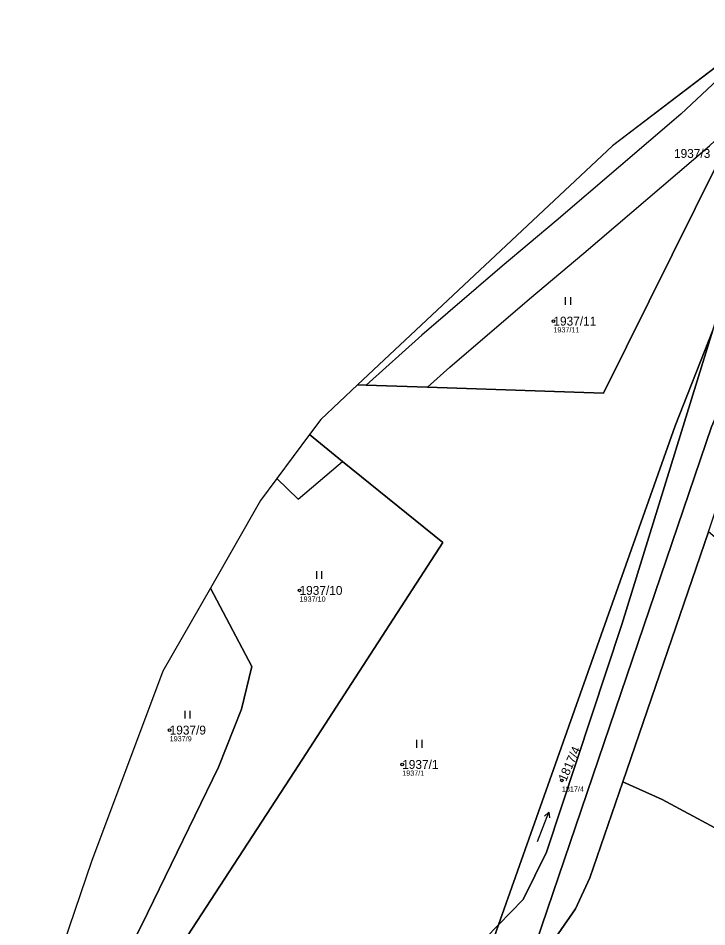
# Model space of a CAD drawing. Extents: x -762274 to -759271, y -1061928 to -1059060.
# Drawn here: x -761676.8 to -761545, y -1061110.9 to -1060936.9 of the extents above; entities that cross this region are included whole.
import ezdxf

# ---------------------------------------------------------------- set-up
doc = ezdxf.new("R2010")
doc.units = 0
for name, color, linetype in [('Definiční body', 7, 'Continuous'), ('Hranice parcel', 7, 'Continuous'), ('Parcelní čísla', 7, 'Continuous'), ('Polygon ku', 7, 'Continuous'), ('Polygon parcely', 7, 'Continuous'), ('Věcná břemena k části', 7, 'Continuous'), ('Značky kultur', 7, 'Continuous')]:
    doc.layers.add(name, color=color, linetype=linetype)

msp = doc.modelspace()

# ---------------------------------------------------------------- linework, layer by layer
at = {"layer": 'Definiční body'}
for centre in [(-761574.37, -1060994.9), (-761622.98, -1061046.45), (-761647.85, -1061073.19), (-761603.32, -1061079.77), (-761572.74, -1061082.82)]:
    msp.add_circle(centre, 0.25, dxfattribs=at)
at = {"layer": 'Hranice parcel'}
for p, q in [((-761530.99, -1060936.9), (-761563.04, -1060961.34)), ((-761563.04, -1060961.34), (-761611.9, -1061007.12)), ((-761611.9, -1061007.12), (-761618.93, -1061013.71)), ((-761618.93, -1061013.71), (-761621.08, -1061016.62)), ((-761561.09, -1061083.11), (-761544.65, -1061035.26)), ((-761640.03, -1061045.99), (-761649.18, -1061061.93))]:
    msp.add_line(p, q, dxfattribs=at)
for points in [[(-761529.96, -1060939.02), (-761538.5, -1060955.71), (-761564.75, -1061008.67), (-761598.46, -1061007.56), (-761610.24, -1061007.17), (-761611.9, -1061007.12)], [(-761580.84, -1061120.41), (-761578.73, -1061117.07), (-761544.07, -1061015.12), (-761528.37, -1060979.24)], [(-761584.85, -1061110.5), (-761551.04, -1061014.93), (-761543.87, -1060996.64)], [(-761543.87, -1060996.64), (-761561.28, -1061052.99), (-761575.72, -1061096.53), (-761580.18, -1061105.64), (-761584.85, -1061110.5)], [(-761621.08, -1061016.62), (-761614.73, -1061021.75), (-761595.52, -1061037.25), (-761623.93, -1061081.12), (-761655.13, -1061129.07)], [(-761621.08, -1061016.62), (-761627.31, -1061025.05), (-761630.42, -1061029.26), (-761640.03, -1061045.99)], [(-761665.3, -1061133.96), (-761663.29, -1061130.97), (-761652.11, -1061108.27), (-761638.48, -1061080.32), (-761634.06, -1061069.21), (-761632.14, -1061061.04), (-761640.03, -1061045.99)], [(-761649.18, -1061061.93), (-761662.78, -1061098.32), (-761676.85, -1061139.64)], [(-761561.09, -1061083.11), (-761567.39, -1061101.46), (-761570.16, -1061107.4), (-761576.79, -1061117.01), (-761580.84, -1061120.41)], [(-761522.28, -1061104.91), (-761543.48, -1061091.91), (-761553.56, -1061086.48), (-761561.09, -1061083.11)], [(-761652.06, -1061133.33), (-761641.24, -1061127.91), (-761631.73, -1061125.43), (-761598.48, -1061119.29), (-761592.46, -1061117.03), (-761587.41, -1061113.06), (-761584.85, -1061110.5)], [(-761584.85, -1061110.5), (-761586.2, -1061114.32), (-761599.26, -1061132.85)]]:
    msp.add_lwpolyline(points, dxfattribs=at)
at = {"layer": 'Polygon ku'}
msp.add_lwpolyline([(-761530.99, -1060936.9), (-761563.04, -1060961.34), (-761611.9, -1061007.12), (-761618.93, -1061013.71), (-761621.08, -1061016.62), (-761627.31, -1061025.05), (-761630.42, -1061029.26), (-761640.03, -1061045.99), (-761649.18, -1061061.93), (-761662.78, -1061098.32), (-761676.85, -1061139.64)], dxfattribs=at)
at = {"layer": 'Polygon parcely'}
for points in [[(-761529.96, -1060939.02), (-761530.99, -1060936.9), (-761563.04, -1060961.34), (-761611.9, -1061007.12), (-761610.24, -1061007.17), (-761598.46, -1061007.56), (-761564.75, -1061008.67), (-761538.5, -1060955.71)], [(-761614.73, -1061021.75), (-761595.52, -1061037.25), (-761623.93, -1061081.12), (-761655.13, -1061129.07), (-761652.06, -1061133.33), (-761641.24, -1061127.91), (-761631.73, -1061125.43), (-761598.48, -1061119.29), (-761592.46, -1061117.03), (-761587.41, -1061113.06), (-761584.85, -1061110.5), (-761551.04, -1061014.93), (-761543.87, -1060996.64), (-761528.96, -1060950.6), (-761526.37, -1060946.41), (-761526.48, -1060946.18), (-761529.96, -1060939.02), (-761538.5, -1060955.71), (-761564.75, -1061008.67), (-761598.46, -1061007.56), (-761610.24, -1061007.17), (-761611.9, -1061007.12), (-761618.93, -1061013.71), (-761621.08, -1061016.62)], [(-761526.69, -1060981.53), (-761528.37, -1060979.24), (-761544.07, -1061015.12), (-761578.73, -1061117.07), (-761580.84, -1061120.41), (-761576.79, -1061117.01), (-761570.16, -1061107.4), (-761567.39, -1061101.46), (-761561.09, -1061083.11), (-761544.65, -1061035.26)], [(-761584.85, -1061110.5), (-761580.18, -1061105.64), (-761575.72, -1061096.53), (-761561.28, -1061052.99), (-761543.87, -1060996.64), (-761551.04, -1061014.93)], [(-761627.31, -1061025.05), (-761630.42, -1061029.26), (-761640.03, -1061045.99), (-761632.14, -1061061.04), (-761634.06, -1061069.21), (-761638.48, -1061080.32), (-761652.11, -1061108.27), (-761663.29, -1061130.97), (-761665.3, -1061133.96), (-761667.33, -1061136.97), (-761664.28, -1061139.8), (-761659.59, -1061133.93), (-761655.13, -1061129.07), (-761623.93, -1061081.12), (-761595.52, -1061037.25), (-761614.73, -1061021.75), (-761621.08, -1061016.62)], [(-761501.01, -1061073.43), (-761493.73, -1061045.77), (-761507.53, -1061066.96), (-761544.65, -1061035.26), (-761561.09, -1061083.11), (-761553.56, -1061086.48), (-761543.48, -1061091.91), (-761522.28, -1061104.91), (-761507.59, -1061087.66)], [(-761634.06, -1061069.21), (-761632.14, -1061061.04), (-761640.03, -1061045.99), (-761649.18, -1061061.93), (-761662.78, -1061098.32), (-761676.85, -1061139.64), (-761665.3, -1061133.96), (-761663.29, -1061130.97), (-761652.11, -1061108.27), (-761638.48, -1061080.32)], [(-761630.26, -1061152.12), (-761650.66, -1061155.32), (-761628.15, -1061175.84), (-761608.94, -1061192.88), (-761605.47, -1061196.5), (-761597.75, -1061203.66), (-761596.73, -1061205.16), (-761595.28, -1061201.99), (-761599.63, -1061195.76), (-761522.28, -1061104.91), (-761543.48, -1061091.91), (-761553.56, -1061086.48), (-761561.09, -1061083.11), (-761567.39, -1061101.46), (-761570.16, -1061107.4), (-761576.79, -1061117.01), (-761580.84, -1061120.41), (-761585.59, -1061127.93), (-761583.51, -1061133.64), (-761600.23, -1061150.87), (-761615.03, -1061150)], [(-761641.83, -1061140.97), (-761631.53, -1061136.51), (-761599.26, -1061132.85), (-761586.2, -1061114.32), (-761584.85, -1061110.5), (-761587.41, -1061113.06), (-761592.46, -1061117.03), (-761598.48, -1061119.29), (-761631.73, -1061125.43), (-761641.24, -1061127.91), (-761652.06, -1061133.33), (-761659.78, -1061140.16), (-761667.79, -1061151.98), (-761657.4, -1061143.6), (-761645.04, -1061143.39)]]:
    msp.add_lwpolyline(points, close=True, dxfattribs=at)
msp.add_lwpolyline([(-761543.87, -1060996.64), (-761561.28, -1061052.99), (-761575.72, -1061096.53), (-761580.18, -1061105.64), (-761584.85, -1061110.5), (-761586.2, -1061114.32), (-761599.26, -1061132.85), (-761586.58, -1061125.23), (-761580.84, -1061120.41), (-761578.73, -1061117.07), (-761544.07, -1061015.12)], dxfattribs=at)
at = {"layer": 'Věcná břemena k části'}
for points in [[(-761529.96, -1060939.02), (-761531.95, -1060940.14), (-761534.41, -1060941.51), (-761538.86, -1060944.89), (-761549.94, -1060955.3), (-761573.81, -1060975.67), (-761584.21, -1060984.39), (-761599.55, -1060997.59), (-761610.24, -1061007.17), (-761598.46, -1061007.56), (-761594.17, -1061003.71), (-761578.94, -1060990.61), (-761568.54, -1060981.89), (-761544.49, -1060961.36), (-761538.5, -1060955.71)], [(-761614.73, -1061021.75), (-761621.08, -1061016.62), (-761627.31, -1061025.05), (-761623.26, -1061029.01), (-761615.57, -1061022.47)]]:
    msp.add_lwpolyline(points, close=True, dxfattribs=at)
at = {"layer": 'Značky kultur'}
for p, q in [((-761572.03, -1060991.79), (-761572.03, -1060990.29)), ((-761571.03, -1060991.79), (-761571.03, -1060990.29)), ((-761619.69, -1061044.25), (-761619.69, -1061042.75)), ((-761618.69, -1061044.25), (-761618.69, -1061042.75)), ((-761644.89, -1061070.99), (-761644.89, -1061069.49)), ((-761643.89, -1061070.99), (-761643.89, -1061069.49)), ((-761600.51, -1061076.58), (-761600.51, -1061075.08)), ((-761599.51, -1061076.58), (-761599.51, -1061075.08)), ((-761577.39, -1061094.53), (-761575.24, -1061088.93)), ((-761575.24, -1061088.93), (-761576.06, -1061089.66)), ((-761575.24, -1061088.93), (-761575.12, -1061090.02))]:
    msp.add_line(p, q, dxfattribs=at)

# ---------------------------------------------------------------- texts
at = {"layer": 'Definiční body'}
for s, p in [('1937/11', (-761574.37, -1060997.06)), ('1937/10', (-761622.98, -1061048.61)), ('1937/9', (-761647.85, -1061075.35)), ('1937/1', (-761603.32, -1061081.93)), ('1817/4', (-761572.74, -1061084.98))]:
    msp.add_text(s, height=1, dxfattribs=at).set_placement(p)
at = {"layer": 'Parcelní čísla'}
for s, p in [('1937/3', (-761551.28, -1060963.65)), ('1937/11', (-761574.37, -1060995.75)), ('1937/10', (-761622.98, -1061047.3)), ('1937/9', (-761647.85, -1061074.04)), ('1937/1', (-761603.32, -1061080.62))]:
    msp.add_text(s, height=1.7, dxfattribs=at).set_placement(p)
msp.add_text('1817/4', height=1.7, rotation=66, dxfattribs=at).set_placement((-761571.96, -1061083.17))

doc.saveas('drawing.dxf')
